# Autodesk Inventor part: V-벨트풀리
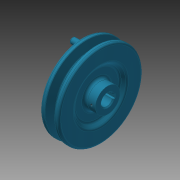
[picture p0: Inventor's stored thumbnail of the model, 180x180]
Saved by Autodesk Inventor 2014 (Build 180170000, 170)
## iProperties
Company: 한국ATC센터
Created: 2015-12
Part Number: V-벨트풀리
Document SubType Name: Modeling
Designer: mdu
Density: 7.25 g/cm^3
Mass: 596.621 g
Surface Area: 212.231 cm^2
Volume: 82.2926 cm^3
Material: 주철
Appearance: 터키옥색
Author: mdu
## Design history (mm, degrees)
sketch "스케치1"
  geometry: L1 (-13, 0)-(13, 0); L2 (-13, 0)-(-13, 12.5); L3 (-13, 12.5)-(-9, 12.5); L4 (-9, 12.5)-(-9, 23); L5 (-9, 23)-(-13, 27); L6 (-13, 27)-(-13, 42.7); L7 (-13, 42.7)-(-8.325, 42.7); L8 (-8.325, 42.7)-(-5.574, 33.7); L9 (-5.574, 33.7)-(-1.426, 33.7); L10 (-1.426, 33.7)-(1.325, 42.7); L11 (1.325, 42.7)-(6, 42.7); L12 (6, 42.7)-(6, 27); L13 (6, 27)-(2, 23); L14 (2, 23)-(2, 12.5); L15 (2, 12.5)-(13, 12.5); L16 (13, 12.5)-(13, 0); L17 (-7.5, 40)-(0.5, 40); 2 further points
  constraints: 34 end point, 6 parallel, 5 collinear, 5 equal length, 4 perpendicular, 2 point on line, 1 coincident, 1 horizontal, 1 midpoint
  dimensions: "d0" = 26 distance of L1.start L1.end; "d1" = 2.7 distance between parallel lines of L7 L17; "d2" = 6.3 distance between parallel lines of L9 L17; "d3" = 8 distance of L17.start L17.end; "d4" = 34 deg angle of L10 L8; "d5" = 19 distance between parallel lines of L12 L6; "d7" = 25 diameter of L15 L1; "d8" = 46 diameter of L13.end L1; "d9" = 54 diameter of L12.end L1; "d10" = 4 distance between parallel lines of L2 L4; "d11" = 80 diameter of L17 L1
revolve "회전1" sketch "스케치1" stored, may be unused: angle "d12" = 90 deg
sketch "스케치2"
  geometry: L1 (-2, 5.657)-(-2, 7.8); L2 (-2, 7.8)-(2, 7.8); L3 (2, 7.8)-(2, 5.657); A1 r 6 centre (0, 0) between (-2, 5.657) and (2, 5.657); 1 further point
  constraints: 6 end point, 2 parallel, 2 point on circle, 1 centre point, 1 coincident, 1 perpendicular, 1 vertical
  dimensions: "d13" = 12 diameter of A1; "d14" = 13.8 dimension on A1 L2; "d15" = 4 distance of L1.end L2.end
extrude "돌출1" cut sketch "스케치2" stored distance "d16" = 10; taper "d17" = 0 deg
node "작업 평면1"
sketch "스케치3"
  geometry: L1 (-5.5, 12.5)-(-5.5, -12.5) reference; L2 (20.5, 27)-(20.5, -27) reference; 3 further points
  constraints: 1 horizontal alignment, 1 midpoint
  dimensions: "d18" = 4 distance from line of point (-1.5, 0) L1; "d33" = 22 distance from line of point (-1.5, 0) L2 (derived)
hole "구멍1" sketch "스케치3" at (-1.5, 0) diameter "d19" = 2.459; stored, may be unused: countersink angle "d23" = 90 deg, drill point angle "d25" = 118 deg; dims "d20" = 6, "d21" = 4, "d22" = 2, "d24" = 8
fillet "모깎기1" dims "d26" = 2, "d27" = 0.5, "d28" = 1, "d29" = 3
chamfer "모따기1" distance "d30" = 1; stored, may be unused: second distance "d31" = 2, angle "d32" = 45 deg
sketch "스케치4" dims "d35" = 70
  geometry: C1 r 3 at (35, 0); 2 further points
  constraints: 2 horizontal alignment, 1 centre point, 1 coincident, 2 other
  dimensions: "d34" = 6 diameter of C1
extrude "돌출2" join sketch "스케치4" distance "d36" = 10; taper "d37" = 0 deg
fillet "모깎기2" dims "d38" = 0.5, "d39" = 1
node "솔리드1"
